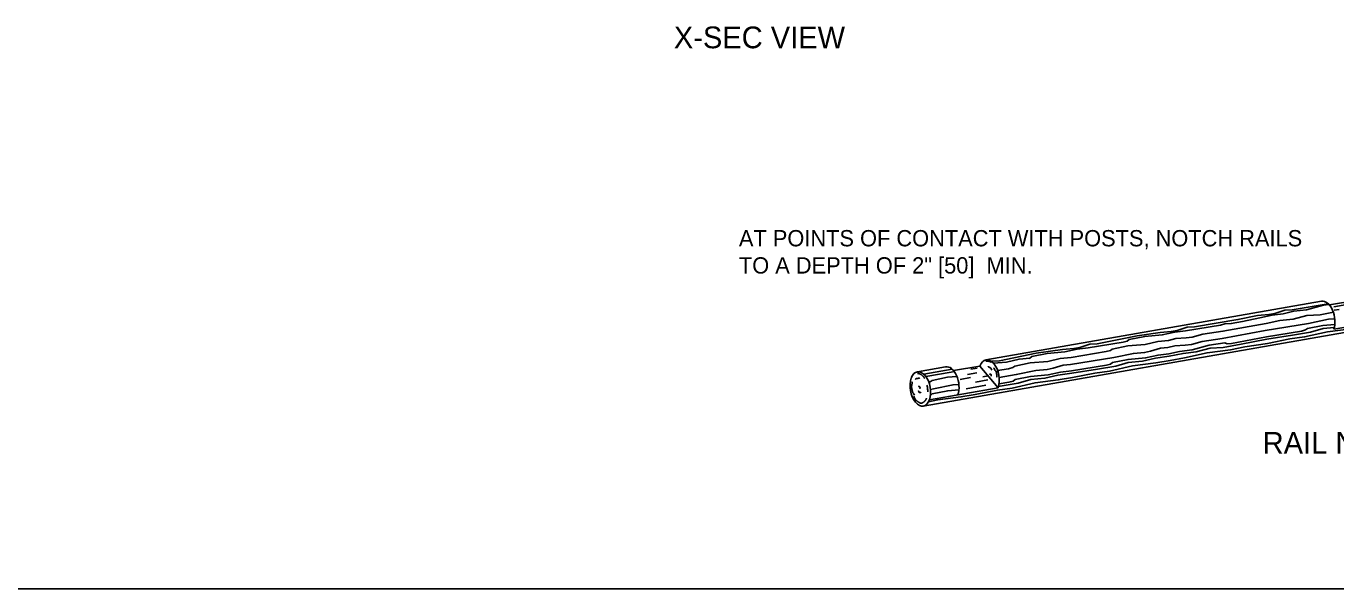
# Model space of a CAD drawing. Extents: x 49991 to 50288, y 49919 to 50011.
# Drawn here: x 50008.695 to 50013.515, y 49993.399 to 49995.469 of the extents above; entities that cross this region are included whole.
import ezdxf

# ---------------------------------------------------------------- set-up
doc = ezdxf.new("R2010")
doc.units = 0
doc.layers.add('Level 1', color=7, linetype='Continuous')
doc.layers.add('Level 2', color=7, linetype='Continuous')

msp = doc.modelspace()

# ---------------------------------------------------------------- linework, layer by layer
at = {"layer": 'Level 1'}
for p, q in [((50011.99659806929, 49994.071617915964), (50015.16942838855, 49994.62561108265)), ((50012.22725165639, 49994.24133800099), (50013.46243389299, 49994.45712163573)), ((50013.58861740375, 49994.46041083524), (50013.491180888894, 49994.44339872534)), ((50013.58989740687, 49994.451090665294), (50013.50694166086, 49994.43657188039)), ((50013.52746068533, 49994.42707639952), (50013.50896566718, 49994.42387381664)), ((50013.506932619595, 49994.354171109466), (50013.655524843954, 49994.38012882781)), ((50011.97527082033, 49994.19760813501), (50012.07812082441, 49994.215576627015)), ((50012.10795061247, 49994.20174077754), (50012.20489587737, 49994.21867696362)), ((50012.15862222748, 49994.18725716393), (50012.19355600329, 49994.19338512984)), ((50012.171085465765, 49994.20686547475), (50012.1948570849, 49994.211056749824)), ((50012.20489587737, 49994.21867696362), (50012.27190336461, 49994.138685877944)), ((50012.019057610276, 49994.09451412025), (50012.27190336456, 49994.138685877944)), ((50012.1321909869, 49994.16946689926), (50012.17070341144, 49994.17619475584)), ((50012.15415710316, 49994.135106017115), (50012.22707442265, 49994.14790967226)), ((50012.18810952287, 49994.159265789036), (50012.23465710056, 49994.167398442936)), ((50012.215818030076, 49994.17927761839), (50012.23505820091, 49994.18267018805)), ((49999.3835, 49993.399000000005), (50016.750100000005, 49993.399000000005))]:
    msp.add_line(p, q, dxfattribs=at)
for points in [[(50012.994684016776, 49994.36342187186), (50013.15412546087, 49994.38971971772), (50013.22661597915, 49994.40481424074), (50013.26780531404, 49994.407946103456), (50013.289660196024, 49994.41252115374), (50013.32669040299, 49994.42393498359), (50013.35337270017, 49994.426011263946)], [(50013.48920207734, 49994.445590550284), (50013.46896395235, 49994.44270645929), (50013.40653064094, 49994.42595100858), (50013.35954549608, 49994.42021235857), (50013.32062361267, 49994.41054029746)], [(50013.35337270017, 49994.426011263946), (50013.48677693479, 49994.44804815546)], [(50012.96188166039, 49994.34786193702), (50013.09057178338, 49994.36911481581), (50013.10607383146, 49994.373422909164), (50013.1299402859, 49994.37515941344), (50013.1707218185, 49994.38260477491), (50013.2345110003, 49994.39590050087), (50013.28066226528, 49994.40643146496), (50013.32062361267, 49994.41054029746)], [(50013.25500998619, 49994.34914244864), (50013.41444712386, 49994.37548154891), (50013.4870364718, 49994.390628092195), (50013.510913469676, 49994.392411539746)], [(50013.50572382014, 49994.416558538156), (50013.456405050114, 49994.40740679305), (50013.40802986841, 49994.40479680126), (50013.357601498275, 49994.39169246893), (50013.30887380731, 49994.385667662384), (50013.25816156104, 49994.37568234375)], [(50012.60313755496, 49994.2852042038), (50012.731846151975, 49994.30647986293), (50012.74735035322, 49994.31076732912), (50012.75458907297, 49994.31613123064), (50012.81132424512, 49994.32774615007), (50012.875791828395, 49994.33320366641), (50012.9219843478, 49994.343738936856), (50012.96188166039, 49994.34786193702)], [(50012.63594421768, 49994.3007228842), (50012.783251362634, 49994.32966401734), (50012.86795222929, 49994.34218574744), (50012.90910246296, 49994.34529267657), (50012.93097581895, 49994.34989050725), (50012.967921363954, 49994.36131635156), (50012.994684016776, 49994.36342187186)], [(50013.25500998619, 49994.34914244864), (50013.09605223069, 49994.319809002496), (50013.02260622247, 49994.309473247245), (50012.982928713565, 49994.29845034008), (50012.960765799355, 49994.2954278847), (50012.92217096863, 49994.29360944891), (50012.89633422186, 49994.28642929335)], [(50013.25816156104, 49994.37568234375), (50013.099220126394, 49994.34639230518), (50013.02573501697, 49994.3360316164), (50012.986080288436, 49994.32499023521), (50012.96393584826, 49994.321990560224), (50012.92528559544, 49994.3201037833), (50012.89945870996, 49994.313028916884)], [(50013.259071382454, 49994.325816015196), (50013.38772886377, 49994.34698207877), (50013.40323091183, 49994.351290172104), (50013.41046532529, 49994.3566953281), (50013.46726022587, 49994.36833733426), (50013.510922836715, 49994.37204660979)], [(50013.260404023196, 49994.31784371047), (50013.354972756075, 49994.332177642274), (50013.42186590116, 49994.34316389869), (50013.468326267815, 49994.35712599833), (50013.50898021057, 49994.3608619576)], [(50013.26320168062, 49994.301829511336), (50013.34562283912, 49994.318273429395), (50013.39945384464, 49994.32574843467), (50013.48409403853, 49994.3449053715), (50013.569207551, 49994.35533304), (50013.62181771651, 49994.364515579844)], [(50012.2772001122, 49994.23806515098), (50012.41194703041, 49994.26634254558), (50012.50921243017, 49994.279486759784), (50012.55039961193, 49994.28263924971), (50012.572229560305, 49994.287253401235), (50012.60920434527, 49994.2985988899), (50012.63594421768, 49994.3007228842)], [(50012.38472118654, 49994.246974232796), (50012.38869090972, 49994.24809758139), (50012.39590900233, 49994.25345932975), (50012.452625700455, 49994.26505146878), (50012.51704987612, 49994.27052530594), (50012.56325871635, 49994.28110398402), (50012.60313755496, 49994.2852042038)], [(50012.537730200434, 49994.22382788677), (50012.69708913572, 49994.25011711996), (50012.76967633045, 49994.26528429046), (50012.81080163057, 49994.26843032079), (50012.83269776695, 49994.27300967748), (50012.86964761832, 49994.28439426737), (50012.89633422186, 49994.28642929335)], [(50012.54074384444, 49994.25029082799), (50012.669386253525, 49994.271601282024), (50012.684956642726, 49994.27585395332), (50012.69212702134, 49994.2812732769), (50012.74894900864, 49994.29285555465), (50012.81337533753, 49994.29830876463), (50012.85954507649, 49994.30886250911), (50012.89945870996, 49994.313028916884)], [(50013.259071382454, 49994.325816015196), (50013.13082528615, 49994.30210725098), (50013.114748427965, 49994.30090865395), (50013.106193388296, 49994.303560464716), (50013.048781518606, 49994.29523207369), (50012.986368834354, 49994.27847877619), (50012.93934028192, 49994.27275644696), (50012.90043471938, 49994.263127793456)], [(50013.260404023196, 49994.31784371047), (50013.16670771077, 49994.29934704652), (50013.10004564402, 49994.28694612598), (50013.05162920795, 49994.28433182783), (50013.00124639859, 49994.271190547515), (50012.95245036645, 49994.26522116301), (50012.90180646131, 49994.25518042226)], [(50013.26320168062, 49994.301829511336), (50013.18017285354, 49994.28940914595), (50013.12690735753, 49994.27811470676), (50013.040874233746, 49994.26750763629), (50012.95722629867, 49994.24843342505), (50012.90457703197, 49994.23922595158)], [(50012.24809207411, 49994.23525606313), (50012.25047656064, 49994.23598456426), (50012.2772001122, 49994.23806515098)], [(50012.25450038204, 49994.229398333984), (50012.30258045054, 49994.233437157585), (50012.348764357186, 49994.24405493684), (50012.38869090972, 49994.24809758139)], [(50012.270102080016, 49994.202188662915), (50012.31064645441, 49994.208902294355), (50012.32615280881, 49994.213169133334), (50012.33341000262, 49994.21855581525), (50012.390182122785, 49994.23021629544), (50012.45460629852, 49994.23569013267), (50012.50080312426, 49994.24618414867), (50012.54074384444, 49994.25029082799)], [(50012.541777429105, 49994.200437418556), (50012.67035240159, 49994.22159486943), (50012.68592403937, 49994.22603533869), (50012.69305101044, 49994.231470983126), (50012.74985237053, 49994.24305110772), (50012.814287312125, 49994.248421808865), (50012.86052108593, 49994.258961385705), (50012.90043471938, 49994.263127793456)], [(50012.54311993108, 49994.19257040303), (50012.637542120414, 49994.20690988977), (50012.704518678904, 49994.21769633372), (50012.75099106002, 49994.231743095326), (50012.802759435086, 49994.23660481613), (50012.85075853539, 49994.24741207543), (50012.90180646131, 49994.25518042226)], [(50012.545876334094, 49994.1765518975), (50012.628219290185, 49994.19294594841), (50012.68218267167, 49994.200351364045), (50012.76677299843, 49994.21958650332), (50012.85194839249, 49994.230020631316), (50012.90457703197, 49994.23922595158)], [(50011.997945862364, 49994.189266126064), (50012.10332053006, 49994.20665429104)], [(50012.00573480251, 49994.18068407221), (50012.09939366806, 49994.19613118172), (50012.110492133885, 49994.19847826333)], [(50012.27338187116, 49994.14334277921), (50012.278951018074, 49994.14418471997), (50012.34589187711, 49994.15511340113), (50012.39234578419, 49994.16913738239), (50012.4440978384, 49994.17395569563), (50012.492078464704, 49994.18474017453), (50012.54311993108, 49994.19257040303)], [(50012.27538613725, 49994.15303692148), (50012.3117440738, 49994.159034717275), (50012.3272027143, 49994.16335913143), (50012.334464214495, 49994.16870455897), (50012.3912015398, 49994.180298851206), (50012.45564203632, 49994.185816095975), (50012.50181823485, 49994.196307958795), (50012.541777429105, 49994.200437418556)], [(50012.27576637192, 49994.1770903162), (50012.33842538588, 49994.18748862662), (50012.411051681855, 49994.202680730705), (50012.452169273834, 49994.20570084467), (50012.47405249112, 49994.21040396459), (50012.51100880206, 49994.22172667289), (50012.537730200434, 49994.22382788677)], [(50012.01714913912, 49994.15891349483), (50012.021537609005, 49994.16012505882), (50012.0287286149, 49994.16554653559), (50012.085525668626, 49994.17716791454), (50012.12043821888, 49994.18010331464)], [(50012.023032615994, 49994.1327934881), (50012.033756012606, 49994.134564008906), (50012.10634966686, 49994.14966929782), (50012.127429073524, 49994.15128582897)], [(50012.1872495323, 49994.11396896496), (50012.269605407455, 49994.13023925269), (50012.32356878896, 49994.1376446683), (50012.40812556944, 49994.15700141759), (50012.49322491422, 49994.167365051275), (50012.545876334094, 49994.1765518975)], [(50012.01541111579, 49994.086572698), (50012.04948675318, 49994.094333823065), (50012.134705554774, 49994.104751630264), (50012.1872495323, 49994.11396896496)], [(50012.022833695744, 49994.11055501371), (50012.02980900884, 49994.11584397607), (50012.086651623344, 49994.12742840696), (50012.127497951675, 49994.130884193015)]]:
    msp.add_lwpolyline(points, dxfattribs=at)
for centre, ratio, start_param, end_param in [((50013.4734500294, 49994.39421114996), 0.5774931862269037, 3.925707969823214, 6.306125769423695), ((50012.23831388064, 49994.178446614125), 0.5774931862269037, 3.9315222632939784, 7.063530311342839), ((50011.98557350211, 49994.134564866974), 0.5774931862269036, 3.9256121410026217, 7.063370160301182), ((50012.09000087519, 49994.152813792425), 0.5774931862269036, 3.9254893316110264, 6.306125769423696), ((50011.985566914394, 49994.13454687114), 0.5774931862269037, 0.7858875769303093, 3.9259797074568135)]:
    msp.add_ellipse(centre, major_axis=(-0.011049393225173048, 0.06292576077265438), ratio=ratio, start_param=start_param, end_param=end_param, dxfattribs=at)
for points in [[(50012.24633045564, 49994.231756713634), (50012.24423931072, 49994.23381129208), (50012.2381945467, 49994.23578680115), (50012.23482042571, 49994.236748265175), (50012.23053031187, 49994.23669662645), (50012.22657725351, 49994.23601290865)], [(50011.97488500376, 49994.19131084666), (50011.97864367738, 49994.1906605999), (50011.9833964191, 49994.189676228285), (50011.98612248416, 49994.1887305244), (50011.98916928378, 49994.18710933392), (50011.99121056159, 49994.185132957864), (50011.99323857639, 49994.18288412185), (50011.99634316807, 49994.180309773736), (50011.99734210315, 49994.179329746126), (50011.99871254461, 49994.177387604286), (50012.000067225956, 49994.174797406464), (50012.00039747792, 49994.17383098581)], [(50012.235212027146, 49994.2164167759), (50012.23634062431, 49994.21599243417), (50012.24114650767, 49994.213699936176), (50012.24447946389, 49994.210336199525), (50012.24734819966, 49994.20742445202), (50012.24825235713, 49994.20355696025)], [(50012.24005617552, 49994.1883683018), (50012.24025041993, 49994.188536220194), (50012.24035133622, 49994.18861937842), (50012.240402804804, 49994.18866074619), (50012.24045497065, 49994.18870196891), (50012.240609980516, 49994.18880984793), (50012.24077099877, 49994.18889674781), (50012.24110812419, 49994.189014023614), (50012.241822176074, 49994.189067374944), (50012.242550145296, 49994.18896464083), (50012.24290466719, 49994.188886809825), (50012.24324505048, 49994.18880843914), (50012.243473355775, 49994.18875474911), (50012.24370024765, 49994.188694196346), (50012.244147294, 49994.188539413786), (50012.24458119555, 49994.18831791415), (50012.24479165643, 49994.18817396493), (50012.2448949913, 49994.18809225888), (50012.2449969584, 49994.18800351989), (50012.24525687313, 49994.18775290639), (50012.24549237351, 49994.18749564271), (50012.24588135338, 49994.1869570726), (50012.24614634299, 49994.18637962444), (50012.2462268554, 49994.186073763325), (50012.246269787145, 49994.18575511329), (50012.24630992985, 49994.1850009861), (50012.24632367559, 49994.184250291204), (50012.24631426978, 49994.183501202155), (50012.24628495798, 49994.182751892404), (50012.246262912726, 49994.18229460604), (50012.246241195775, 49994.18183736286), (50012.24621660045, 49994.18138031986), (50012.24618592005, 49994.18092363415)], [(50012.267480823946, 49994.17755995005), (50012.267403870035, 49994.17769788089), (50012.267069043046, 49994.185899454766), (50012.26628683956, 49994.19019671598), (50012.26550635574, 49994.19647509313), (50012.25989923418, 49994.203646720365), (50012.25724167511, 49994.20972915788), (50012.25573183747, 49994.2124074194)], [(50011.95543534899, 49994.160124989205), (50011.95539052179, 49994.157782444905), (50011.95535459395, 49994.15661359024), (50011.95525570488, 49994.15544974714), (50011.95478428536, 49994.15184016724), (50011.95427788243, 49994.14823715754), (50011.95396270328, 49994.14666490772), (50011.95356686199, 49994.145101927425), (50011.953232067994, 49994.143532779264), (50011.953131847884, 49994.14274106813), (50011.953106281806, 49994.14234258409), (50011.95310003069, 49994.14194202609), (50011.95327278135, 49994.140515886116), (50011.953660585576, 49994.13912094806), (50011.95411264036, 49994.13773372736), (50011.954315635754, 49994.137035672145), (50011.954478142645, 49994.136330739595), (50011.954955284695, 49994.13373214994), (50011.95543759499, 49994.13113449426), (50011.956281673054, 49994.12711210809), (50011.95678447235, 49994.12511816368), (50011.95706785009, 49994.12412760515), (50011.957377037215, 49994.12314212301), (50011.958512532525, 49994.12054802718), (50011.96000513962, 49994.11814091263), (50011.96445351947, 49994.11168240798)], [(50011.966185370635, 49994.16900684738), (50011.96716886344, 49994.16970437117), (50011.9717591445, 49994.17240277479), (50011.97641232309, 49994.173280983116), (50011.980431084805, 49994.1740276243), (50011.98414177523, 49994.17261137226)], [(50011.97851611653, 49994.143169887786), (50011.978545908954, 49994.1431937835), (50011.97859807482, 49994.14323500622), (50011.97875308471, 49994.14334288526), (50011.97891410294, 49994.14342978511), (50011.97925122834, 49994.14354706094), (50011.97942611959, 49994.143580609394), (50011.97960396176, 49994.14360148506), (50011.97996528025, 49994.14360041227), (50011.980150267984, 49994.143582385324), (50011.98033265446, 49994.14356021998), (50011.98051334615, 49994.14353246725), (50011.98069324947, 49994.14349767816), (50011.98104777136, 49994.14341984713), (50011.98138815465, 49994.14334147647), (50011.98161645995, 49994.14328778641), (50011.981843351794, 49994.143227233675), (50011.98229039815, 49994.143072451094), (50011.98272429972, 49994.14285095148), (50011.98293476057, 49994.14270700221), (50011.98303809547, 49994.14262529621), (50011.98314006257, 49994.14253655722), (50011.9833999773, 49994.14228594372), (50011.983635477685, 49994.14202868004), (50011.98384081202, 49994.14176818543), (50011.98393497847, 49994.14163151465), (50011.984024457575, 49994.1414901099), (50011.984173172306, 49994.141208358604), (50011.984289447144, 49994.140912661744), (50011.984369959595, 49994.140606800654), (50011.98441289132, 49994.140288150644), (50011.98445303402, 49994.13953402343), (50011.98446677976, 49994.13878332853), (50011.98445737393, 49994.13803423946), (50011.98442806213, 49994.137284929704), (50011.9844060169, 49994.13682764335), (50011.984384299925, 49994.13637040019), (50011.98437258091, 49994.13614192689)], [(50012.01321925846, 49994.12351668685), (50012.013532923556, 49994.126378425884), (50012.012830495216, 49994.129386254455), (50012.01188304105, 49994.136666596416), (50012.01173960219, 49994.13859547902), (50012.01132985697, 49994.144195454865), (50012.008989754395, 49994.14801358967)], [(50011.961444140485, 49994.107472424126), (50011.96400015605, 49994.10196324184), (50011.9645439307, 49994.10085613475), (50011.96512251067, 49994.099767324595), (50011.96572760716, 49994.098690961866), (50011.966350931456, 49994.097621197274), (50011.967236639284, 49994.09621269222), (50011.96820517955, 49994.09486503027), (50011.96926451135, 49994.09358377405), (50011.96983071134, 49994.09296978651), (50011.97042259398, 49994.09237448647), (50011.97275922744, 49994.0903359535), (50011.97522925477, 49994.08847646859), (50011.976797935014, 49994.087365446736), (50011.97838188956, 49994.08629313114), (50011.979990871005, 49994.0852545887), (50011.981634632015, 49994.084244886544), (50011.98261958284, 49994.083698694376), (50011.983626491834, 49994.083225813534), (50011.98467486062, 49994.08281296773), (50011.98522068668, 49994.08262490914), (50011.98578419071, 49994.082446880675), (50011.98675594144, 49994.08220285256), (50011.98772036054, 49994.08206367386), (50011.988674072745, 49994.0820335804), (50011.98914585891, 49994.08206076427), (50011.98961370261, 49994.08211680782), (50011.99086347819, 49994.0823719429), (50011.99209948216, 49994.082748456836), (50011.99391301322, 49994.08351355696), (50011.99450338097, 49994.083815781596), (50011.99557436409, 49994.08440226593), (50011.996605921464, 49994.085015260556), (50011.99854712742, 49994.086427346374), (50011.99936127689, 49994.08718637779), (50012.00015591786, 49994.08796137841), (50012.00170334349, 49994.08955097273), (50012.00235265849, 49994.09024042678), (50012.003015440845, 49994.090923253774), (50012.00431504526, 49994.09230719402), (50012.00546943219, 49994.09377912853), (50012.006345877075, 49994.095415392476), (50012.00732139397, 49994.09795233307), (50012.00823647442, 49994.10044106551)], [(50011.98732420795, 49994.12213888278), (50011.987194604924, 49994.12191722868), (50011.98712595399, 49994.12180593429), (50011.98709060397, 49994.12175016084), (50011.987054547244, 49994.121694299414), (50011.98694268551, 49994.1215421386), (50011.98681836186, 49994.12140789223), (50011.98653717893, 49994.12118802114), (50011.985878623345, 49994.120906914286), (50011.985156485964, 49994.12076903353), (50011.98479582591, 49994.1207281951), (50011.98444837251, 49994.120692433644), (50011.984214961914, 49994.12066951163), (50011.98398067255, 49994.120653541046), (50011.98350759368, 49994.12065564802), (50011.9830254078, 49994.12072514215), (50011.98277973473, 49994.120793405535), (50011.98265554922, 49994.12083735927), (50011.982530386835, 49994.12088841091), (50011.9822034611, 49994.12104165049), (50011.981897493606, 49994.12120906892), (50011.98135541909, 49994.12159315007), (50011.98091813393, 49994.12205407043), (50011.98074315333, 49994.12231753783), (50011.98059960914, 49994.12260524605), (50011.98031806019, 49994.12330599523), (50011.98006260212, 49994.1240120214), (50011.97982957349, 49994.12472400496), (50011.97961531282, 49994.12544262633), (50011.979488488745, 49994.12588252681), (50011.97936136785, 49994.126322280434), (50011.97923703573, 49994.12676277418), (50011.97911857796, 49994.12720489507)]]:
    msp.add_spline(points, degree=3, dxfattribs=at)

# ---------------------------------------------------------------- texts
at = {"layer": 'Level 2'}
for s, height, p in [('X-SEC VIEW', 0.07999999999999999, (50011.078605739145, 49995.387899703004)), ('AT POINTS OF CONTACT WITH POSTS, NOTCH RAILS', 0.05999999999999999, (50011.31805790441, 49994.65899961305)), ('TO A DEPTH OF 2" [50]  MIN. ', 0.05999999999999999, (50011.31805790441, 49994.55899961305)), ('RAIL NOTCHING', 0.08000000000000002, (50013.245443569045, 49993.89595814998))]:
    msp.add_text(s, height=height, dxfattribs=at).set_placement(p)

doc.saveas('drawing.dxf')
